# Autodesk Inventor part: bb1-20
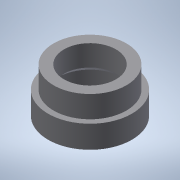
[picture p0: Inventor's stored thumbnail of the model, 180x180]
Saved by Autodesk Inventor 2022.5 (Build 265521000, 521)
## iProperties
Created: 2016-12
Part Number: bb1-20
Material: 一般
Document SubType Name: Modeling
Designer: imaocorp
Density: 1 g/cm^3
Appearance: 既定
Author: imaocorp
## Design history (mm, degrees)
node "bb1-20.x_t1"
node "bb1-20"
node "Base1"
